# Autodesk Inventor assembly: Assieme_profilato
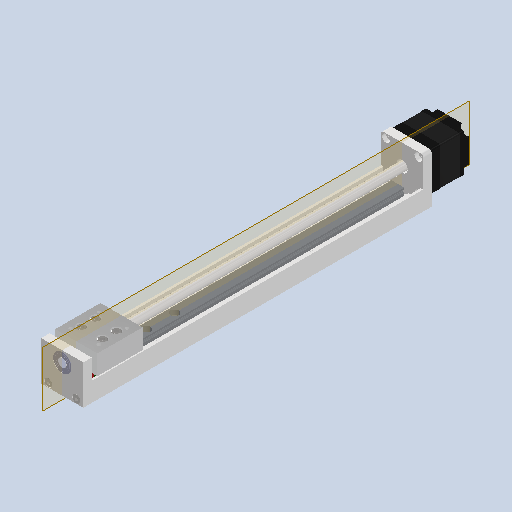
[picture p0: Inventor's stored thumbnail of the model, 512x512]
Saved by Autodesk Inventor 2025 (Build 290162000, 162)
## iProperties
Created: 2025-11
Part Number: Assieme_profilato
Document SubType Name: Assembly
Designer: Ryzen5700u
Author: Ryzen5700u
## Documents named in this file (11)
- C:\Users\Ryzen5700u\Desktop\scara\Assieme_scara_03\Assieme_profilato.iam
- C:\Users\Ryzen5700u\Desktop\scara\Assieme_scara_03\profilato.ipt
- C:\Users\Ryzen5700u\Desktop\scara\Assieme_scara_03\profilato_cuscinetto.ipt
- C:\Users\Ryzen5700u\Desktop\scara\Assieme_scara_03\profilato_motore.ipt
- C:\Users\Ryzen5700u\Desktop\scara\Assieme_scara_03\Nema11.ipt
- C:\Users\Ryzen5700u\Desktop\scara\Assieme_scara_03\00144585.iam
- C:\Users\Ryzen5700u\Desktop\scara\Assieme_scara_03\Actuator_MGN9.ipt
- C:\Users\Ryzen5700u\Desktop\scara\Assieme_scara_03\AS 1420 - 1973 - M3 x 6.ipt
- C:\Users\Ryzen5700u\Desktop\scara\Assieme_scara_03\Actuator_MGN9C.ipt
- C:\Users\Ryzen5700u\Desktop\scara\Assieme_scara_03\Carriage.ipt
- C:\Users\Ryzen5700u\Desktop\scara\Assieme_scara_03\AS 1420 - 1973 - M3 x 12.ipt
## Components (16 placed, 10 different names)
1. profilato:1
2. profilato_cuscinetto:1
3. profilato_motore:1
4. Nema11:1
5. 00144585:1 [sub-assembly]
6. Actuator_MGN9:1
7. AS 1420 - Metrico M3 x 6:1
8. AS 1420 - Metrico M3 x 6:2
9. AS 1420 - Metrico M3 x 6:3
10. AS 1420 - Metrico M3 x 6:4
11. Actuator_MGN9C:1
12. Carriage:1
13. AS 1420 - Metrico M3 x 12:1
14. AS 1420 - Metrico M3 x 12:2
15. AS 1420 - Metrico M3 x 12:3
16. AS 1420 - Metrico M3 x 12:4
